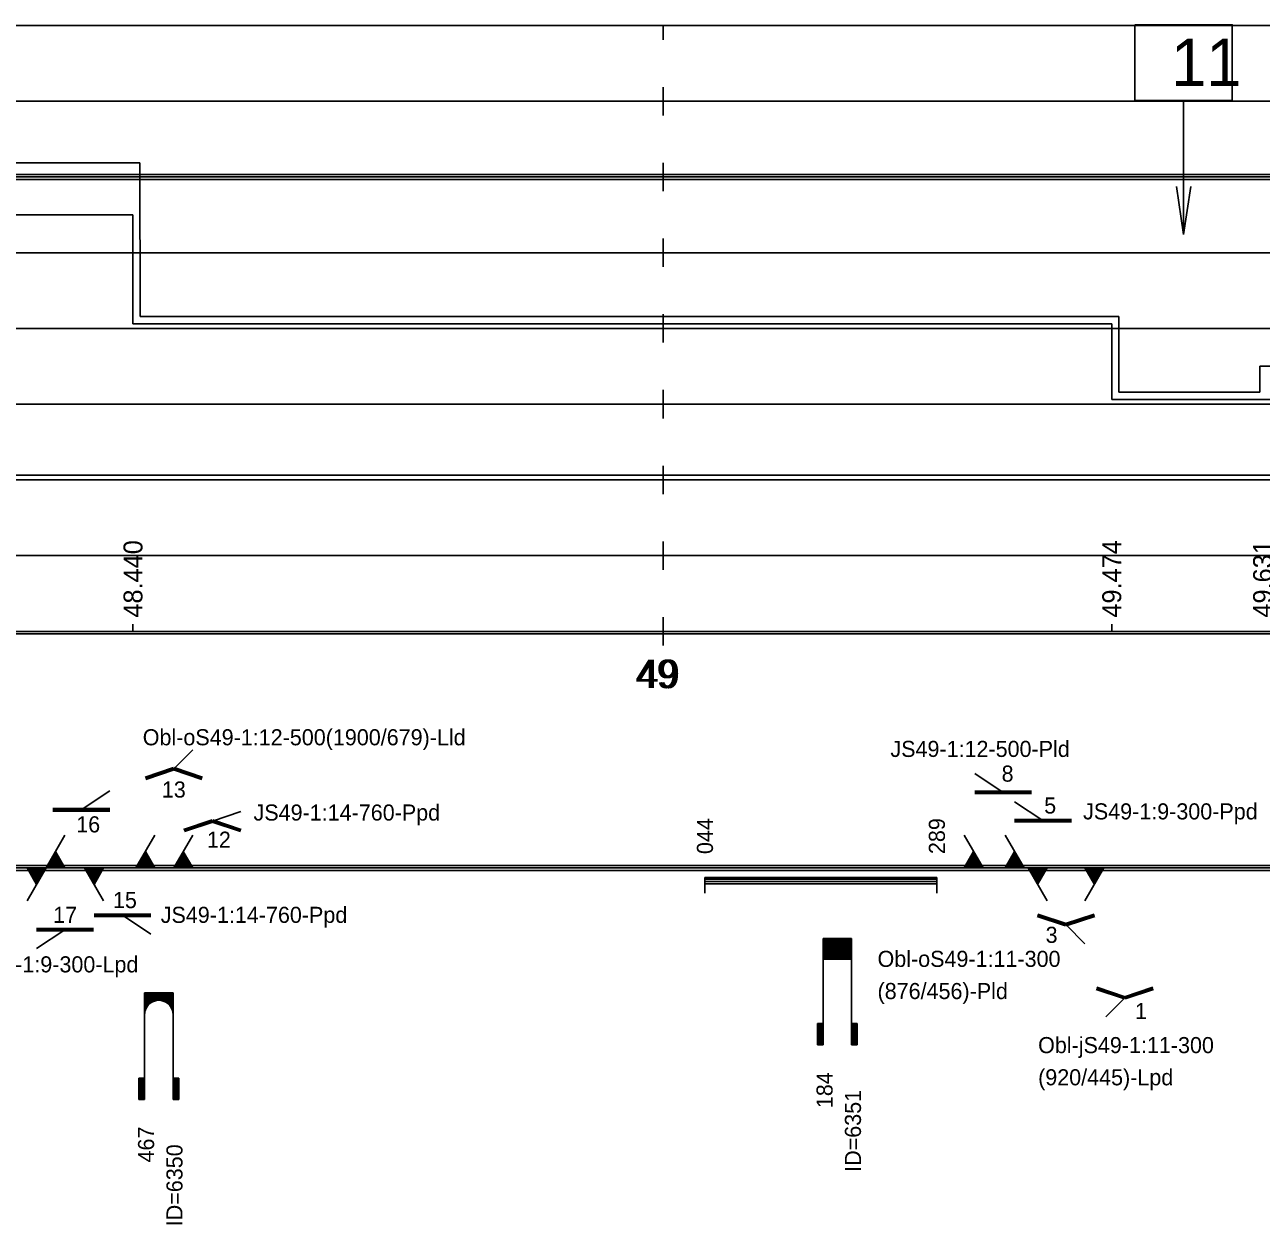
# Model space of a CAD drawing. Extents: x 2 to 10148, y 0 to 380.
# Drawn here: x 5134 to 5264.7, y 87.4 to 214.1 of the extents above; entities that cross this region are included whole.
import ezdxf

# ---------------------------------------------------------------- set-up
doc = ezdxf.new("R2010")
doc.units = 0
for name, color, linetype in [('CARA_S_OBJEKTY', 7, 'Continuous'), ('L_OBJEKTY_TEXT', 7, 'Continuous'), ('L_OBJEKTY_TVAR', 7, 'Continuous'), ('OBJEKTY_TEXT', 7, 'Continuous'), ('OBJEKTY_TVAR', 7, 'Continuous'), ('RYCHL_A', 7, 'Continuous'), ('RYCHL_B', 7, 'Continuous'), ('RYCHL_C', 7, 'Continuous'), ('RYCHL_RASTR', 7, 'Continuous'), ('RYCHL_STAN', 7, 'Continuous'), ('SLOUPEC', 7, 'Continuous'), ('STANIC_ZMEN_V', 7, 'Continuous')]:
    doc.layers.add(name, color=color, linetype=linetype)

msp = doc.modelspace()

# ---------------------------------------------------------------- linework, layer by layer
at = {"layer": 'CARA_S_OBJEKTY'}
for p, q in [((5128.6, 125.25), (5974.91, 125.25)), ((5128.6, 125), (5974.91, 125)), ((5128.6, 124.75), (5974.91, 124.75))]:
    msp.add_line(p, q, dxfattribs=at)
at = {"layer": 'L_OBJEKTY_TVAR'}
for p, q in [((5205.9, 124), (5230.41, 124)), ((5205.9, 122.33), (5205.9, 124)), ((5205.9, 123.83), (5230.41, 123.83)), ((5205.9, 123.58), (5230.41, 123.58)), ((5205.9, 123.33), (5230.41, 123.33)), ((5230.41, 122.33), (5230.41, 124))]:
    msp.add_line(p, q, dxfattribs=at)
at = {"layer": 'OBJEKTY_TVAR'}
for p, q in [((5149.77, 135.48), (5151.77, 137.48)), ((5146.73, 134.6), (5149.73, 135.6)), ((5146.77, 134.48), (5149.77, 135.48)), ((5146.81, 134.36), (5149.81, 135.36)), ((5149.73, 135.36), (5152.73, 134.36)), ((5149.77, 135.48), (5152.77, 134.48)), ((5149.81, 135.6), (5152.81, 134.6)), ((5237.42, 132.99), (5234.42, 134.99)), ((5140, 131.14), (5143, 133.14)), ((5234.42, 133.11), (5240.42, 133.11)), ((5234.42, 132.99), (5240.42, 132.99)), ((5234.42, 132.86), (5240.42, 132.86)), ((5241.62, 130), (5238.62, 132)), ((5137, 131.27), (5143, 131.27)), ((5137, 131.14), (5143, 131.14)), ((5137, 131.02), (5143, 131.02)), ((5153.85, 129.96), (5156.85, 130.96)), ((5150.81, 129.08), (5153.81, 130.08)), ((5150.85, 128.96), (5153.85, 129.96)), ((5150.89, 128.84), (5153.89, 129.84)), ((5153.81, 129.84), (5156.81, 128.84)), ((5153.85, 129.96), (5156.85, 128.96)), ((5153.89, 130.08), (5156.89, 129.08)), ((5238.62, 130.12), (5244.62, 130.12)), ((5238.62, 130), (5244.62, 130)), ((5238.62, 129.88), (5244.62, 129.88)), ((5136.27, 125), (5138.27, 128.46)), ((5145.77, 125), (5147.77, 128.46)), ((5149.77, 125), (5151.77, 128.46)), ((5235.29, 125), (5233.29, 128.46)), ((5239.62, 125), (5237.62, 128.46)), ((5136.92, 125), (5136.59, 125.56)), ((5137.07, 125), (5136.67, 125.69)), ((5137.22, 125), (5136.74, 125.82)), ((5137.37, 125), (5136.82, 125.95)), ((5137.52, 125), (5136.89, 126.08)), ((5137.67, 125), (5136.97, 126.21)), ((5137.82, 125), (5137.04, 126.34)), ((5137.97, 125), (5137.12, 126.47)), ((5138.12, 125), (5137.19, 126.6)), ((5138.27, 125), (5137.27, 126.73)), ((5146.42, 125), (5146.09, 125.56)), ((5146.57, 125), (5146.17, 125.69)), ((5146.72, 125), (5146.24, 125.82)), ((5146.87, 125), (5146.32, 125.95)), ((5147.02, 125), (5146.39, 126.08)), ((5147.17, 125), (5146.47, 126.21)), ((5147.32, 125), (5146.54, 126.34)), ((5147.47, 125), (5146.62, 126.47)), ((5147.62, 125), (5146.69, 126.6)), ((5147.77, 125), (5146.77, 126.73)), ((5150.42, 125), (5150.1, 125.56)), ((5150.57, 125), (5150.17, 125.69)), ((5150.72, 125), (5150.25, 125.82)), ((5150.87, 125), (5150.32, 125.95)), ((5151.02, 125), (5150.4, 126.08)), ((5151.17, 125), (5150.47, 126.21)), ((5151.32, 125), (5150.55, 126.34)), ((5151.47, 125), (5150.62, 126.47)), ((5151.62, 125), (5150.7, 126.6)), ((5151.77, 125), (5150.77, 126.73)), ((5233.29, 125), (5234.29, 126.73)), ((5233.44, 125), (5234.36, 126.6)), ((5233.59, 125), (5234.44, 126.47)), ((5233.74, 125), (5234.51, 126.34)), ((5233.89, 125), (5234.59, 126.21)), ((5234.04, 125), (5234.66, 126.08)), ((5234.19, 125), (5234.74, 125.95)), ((5234.34, 125), (5234.81, 125.82)), ((5234.49, 125), (5234.89, 125.69)), ((5234.64, 125), (5234.96, 125.56)), ((5237.62, 125), (5238.62, 126.73)), ((5237.77, 125), (5238.69, 126.6)), ((5237.92, 125), (5238.77, 126.47)), ((5238.07, 125), (5238.84, 126.34)), ((5238.22, 125), (5238.92, 126.21)), ((5238.37, 125), (5238.99, 126.08)), ((5238.52, 125), (5239.07, 125.95)), ((5238.67, 125), (5239.14, 125.82)), ((5238.82, 125), (5239.22, 125.69)), ((5238.97, 125), (5239.29, 125.56)), ((5134.27, 125), (5135.27, 123.27)), ((5136.27, 125), (5134.27, 121.54)), ((5134.42, 125), (5135.34, 123.4)), ((5134.57, 125), (5135.42, 123.53)), ((5134.72, 125), (5135.49, 123.66)), ((5134.87, 125), (5135.57, 123.79)), ((5135.02, 125), (5135.64, 123.92)), ((5135.17, 125), (5135.72, 124.05)), ((5135.32, 125), (5135.79, 124.18)), ((5135.47, 125), (5135.87, 124.31)), ((5135.62, 125), (5135.94, 124.44)), ((5135.77, 125), (5136.02, 124.57)), ((5135.92, 125), (5136.09, 124.7)), ((5136.07, 125), (5136.17, 124.83)), ((5136.47, 125), (5136.37, 125.17)), ((5136.62, 125), (5136.44, 125.3)), ((5136.77, 125), (5136.52, 125.43)), ((5140.34, 125), (5142.34, 121.54)), ((5140.54, 125), (5140.44, 124.83)), ((5140.69, 125), (5140.51, 124.7)), ((5140.84, 125), (5140.59, 124.57)), ((5140.99, 125), (5140.66, 124.44)), ((5141.14, 125), (5140.74, 124.31)), ((5141.29, 125), (5140.81, 124.18)), ((5141.44, 125), (5140.89, 124.05)), ((5141.59, 125), (5140.96, 123.92)), ((5141.74, 125), (5141.04, 123.79)), ((5141.89, 125), (5141.11, 123.66)), ((5142.04, 125), (5141.19, 123.53)), ((5142.19, 125), (5141.26, 123.4)), ((5142.34, 125), (5141.34, 123.27)), ((5145.97, 125), (5145.87, 125.17)), ((5146.12, 125), (5145.94, 125.3)), ((5146.27, 125), (5146.02, 125.43)), ((5149.97, 125), (5149.87, 125.17)), ((5150.12, 125), (5149.95, 125.3)), ((5150.27, 125), (5150.02, 125.43)), ((5234.79, 125), (5235.04, 125.43)), ((5234.94, 125), (5235.11, 125.3)), ((5235.09, 125), (5235.19, 125.17)), ((5239.12, 125), (5239.37, 125.43)), ((5239.27, 125), (5239.44, 125.3)), ((5239.42, 125), (5239.52, 125.17)), ((5240.06, 125), (5242.06, 121.54)), ((5240.26, 125), (5240.16, 124.83)), ((5240.41, 125), (5240.23, 124.7)), ((5240.56, 125), (5240.31, 124.57)), ((5240.71, 125), (5240.38, 124.44)), ((5240.86, 125), (5240.46, 124.31)), ((5241.01, 125), (5240.53, 124.18)), ((5241.16, 125), (5240.61, 124.05)), ((5241.31, 125), (5240.68, 123.92)), ((5241.46, 125), (5240.76, 123.79)), ((5241.61, 125), (5240.83, 123.66)), ((5241.76, 125), (5240.91, 123.53)), ((5241.91, 125), (5240.98, 123.4)), ((5242.06, 125), (5241.06, 123.27)), ((5246.06, 125), (5247.06, 123.27)), ((5248.06, 125), (5246.06, 121.54)), ((5246.21, 125), (5247.14, 123.4)), ((5246.36, 125), (5247.21, 123.53)), ((5246.51, 125), (5247.29, 123.66)), ((5246.66, 125), (5247.36, 123.79)), ((5246.81, 125), (5247.44, 123.92)), ((5246.96, 125), (5247.51, 124.05)), ((5247.11, 125), (5247.59, 124.18)), ((5247.26, 125), (5247.66, 124.31)), ((5247.41, 125), (5247.74, 124.44)), ((5247.56, 125), (5247.81, 124.57)), ((5247.71, 125), (5247.89, 124.7)), ((5247.86, 125), (5247.96, 124.83)), ((5141.34, 120.12), (5147.34, 120.12)), ((5141.34, 120), (5147.34, 120)), ((5141.34, 119.88), (5147.34, 119.88)), ((5144.34, 120), (5147.34, 118)), ((5241.02, 119.88), (5244.02, 118.88)), ((5241.06, 120), (5244.06, 119)), ((5241.09, 120.12), (5244.09, 119.12)), ((5244.02, 119.12), (5247.02, 120.12)), ((5244.06, 119), (5247.06, 120)), ((5244.06, 119), (5246.06, 117)), ((5244.09, 118.88), (5247.09, 119.88)), ((5135.27, 118.61), (5141.27, 118.61)), ((5135.27, 118.48), (5141.27, 118.48)), ((5138.27, 118.48), (5135.27, 116.48)), ((5135.27, 118.36), (5141.27, 118.36)), ((5218.39, 117.56), (5221.39, 117.56)), ((5218.39, 106.31), (5218.39, 117.56)), ((5218.39, 117.48), (5221.39, 117.48)), ((5218.39, 117.41), (5221.39, 117.41)), ((5218.39, 117.33), (5221.39, 117.33)), ((5218.39, 117.26), (5221.39, 117.26)), ((5218.39, 117.18), (5221.39, 117.18)), ((5218.39, 117.11), (5221.39, 117.11)), ((5218.39, 117.03), (5221.39, 117.03)), ((5218.39, 116.96), (5221.39, 116.96)), ((5218.39, 116.88), (5221.39, 116.88)), ((5218.39, 116.81), (5221.39, 116.81)), ((5218.39, 116.73), (5221.39, 116.73)), ((5218.39, 116.66), (5221.39, 116.66)), ((5218.39, 116.58), (5221.39, 116.58)), ((5218.39, 116.51), (5221.39, 116.51)), ((5218.39, 116.43), (5221.39, 116.43)), ((5218.39, 116.36), (5221.39, 116.36)), ((5221.39, 117.56), (5221.39, 106.31)), ((5218.39, 116.28), (5221.39, 116.28)), ((5218.39, 116.21), (5221.39, 116.21)), ((5218.39, 116.13), (5221.39, 116.13)), ((5218.39, 116.06), (5221.39, 116.06)), ((5218.39, 115.98), (5221.39, 115.98)), ((5218.39, 115.91), (5221.39, 115.91)), ((5218.39, 115.83), (5221.39, 115.83)), ((5218.39, 115.76), (5221.39, 115.76)), ((5218.39, 115.68), (5221.39, 115.68)), ((5218.39, 115.61), (5221.39, 115.61)), ((5218.39, 115.53), (5221.39, 115.53)), ((5218.39, 115.46), (5221.39, 115.46)), ((5218.39, 115.38), (5221.39, 115.38)), ((5247.31, 112.4), (5250.31, 111.4)), ((5250.23, 111.4), (5253.23, 112.4)), ((5146.69, 100.56), (5146.69, 111.81)), ((5149.69, 111.81), (5146.69, 111.81)), ((5146.69, 111.73), (5149.69, 111.73)), ((5146.69, 111.66), (5149.69, 111.66)), ((5146.69, 111.58), (5149.69, 111.58)), ((5146.69, 111.51), (5149.69, 111.51)), ((5146.69, 111.43), (5149.69, 111.43)), ((5146.69, 111.36), (5149.69, 111.36)), ((5146.69, 111.28), (5149.69, 111.28)), ((5146.69, 111.21), (5149.69, 111.21)), ((5146.69, 111.13), (5149.69, 111.13)), ((5149.69, 111.81), (5149.69, 100.56)), ((5247.23, 112.16), (5250.23, 111.16)), ((5247.27, 112.28), (5250.27, 111.28)), ((5250.27, 111.28), (5248.27, 109.28)), ((5250.27, 111.28), (5253.27, 112.28)), ((5250.31, 111.16), (5253.31, 112.16)), ((5146.69, 111.06), (5149.69, 111.06)), ((5146.69, 110.98), (5147.85, 110.98)), ((5146.69, 110.91), (5147.61, 110.91)), ((5146.69, 110.83), (5147.46, 110.83)), ((5146.69, 110.76), (5147.34, 110.76)), ((5146.69, 110.68), (5147.24, 110.68)), ((5146.69, 110.61), (5147.15, 110.61)), ((5146.69, 110.53), (5147.08, 110.53)), ((5146.69, 110.46), (5147.02, 110.46)), ((5146.69, 110.38), (5146.96, 110.38)), ((5146.69, 110.31), (5146.91, 110.31)), ((5146.69, 110.23), (5146.87, 110.23)), ((5146.69, 110.16), (5146.83, 110.16)), ((5146.69, 110.08), (5146.8, 110.08)), ((5146.69, 110.01), (5146.77, 110.01)), ((5146.69, 109.93), (5146.75, 109.93)), ((5146.69, 109.86), (5146.73, 109.86)), ((5146.69, 109.78), (5146.71, 109.78)), ((5146.7, 109.67), (5146.72, 109.84)), ((5146.72, 109.84), (5146.77, 110.02)), ((5146.77, 110.02), (5146.84, 110.17)), ((5146.84, 110.17), (5146.91, 110.31)), ((5146.91, 110.31), (5147.02, 110.46)), ((5147.02, 110.46), (5147.15, 110.61)), ((5147.15, 110.61), (5147.23, 110.68)), ((5147.23, 110.68), (5147.33, 110.75)), ((5147.33, 110.75), (5147.46, 110.83)), ((5147.46, 110.83), (5147.61, 110.91)), ((5147.61, 110.91), (5147.85, 110.98)), ((5147.85, 110.98), (5148.06, 111.02)), ((5148.06, 111.02), (5148.31, 111.02)), ((5148.31, 111.02), (5148.45, 111)), ((5148.45, 111), (5148.53, 110.98)), ((5148.53, 110.98), (5149.69, 110.98)), ((5148.53, 110.98), (5148.77, 110.91)), ((5148.77, 110.91), (5149.69, 110.91)), ((5148.77, 110.91), (5148.92, 110.83)), ((5148.92, 110.83), (5149.69, 110.83)), ((5148.92, 110.83), (5149.04, 110.76)), ((5149.04, 110.76), (5149.69, 110.76)), ((5149.04, 110.76), (5149.14, 110.68)), ((5149.14, 110.68), (5149.69, 110.68)), ((5149.14, 110.68), (5149.23, 110.61)), ((5149.23, 110.61), (5149.69, 110.61)), ((5149.23, 110.61), (5149.3, 110.53)), ((5149.3, 110.53), (5149.69, 110.53)), ((5149.3, 110.53), (5149.36, 110.46)), ((5149.36, 110.46), (5149.68, 110.46)), ((5149.36, 110.46), (5149.42, 110.38)), ((5149.42, 110.38), (5149.69, 110.38)), ((5149.42, 110.38), (5149.51, 110.23)), ((5149.47, 110.31), (5149.69, 110.31)), ((5149.51, 110.23), (5149.69, 110.23)), ((5149.51, 110.23), (5149.58, 110.08)), ((5149.55, 110.16), (5149.69, 110.16)), ((5149.58, 110.08), (5149.69, 110.08)), ((5149.58, 110.08), (5149.63, 109.93)), ((5149.61, 110.01), (5149.69, 110.01)), ((5149.63, 109.93), (5149.69, 109.93)), ((5149.63, 109.93), (5149.67, 109.78)), ((5149.65, 109.86), (5149.69, 109.86)), ((5149.67, 109.78), (5149.69, 109.78)), ((5149.67, 109.78), (5149.69, 109.53)), ((5146.69, 109.71), (5146.7, 109.71)), ((5146.69, 109.53), (5146.7, 109.67)), ((5149.68, 109.71), (5149.69, 109.71)), ((5217.79, 108.56), (5217.79, 106.31)), ((5217.79, 108.56), (5218.39, 108.56)), ((5217.86, 108.56), (5217.86, 106.31)), ((5217.94, 108.56), (5217.94, 106.31)), ((5218.01, 108.56), (5218.01, 106.31)), ((5218.09, 108.56), (5218.09, 106.31)), ((5218.16, 108.56), (5218.16, 106.31)), ((5218.24, 108.56), (5218.24, 106.31)), ((5218.31, 108.56), (5218.31, 106.31)), ((5221.99, 108.56), (5221.39, 108.56)), ((5221.47, 108.56), (5221.47, 106.31)), ((5221.54, 108.56), (5221.54, 106.31)), ((5221.62, 108.56), (5221.62, 106.31)), ((5221.69, 108.56), (5221.69, 106.31)), ((5221.77, 108.56), (5221.77, 106.31)), ((5221.84, 108.56), (5221.84, 106.31)), ((5221.92, 108.56), (5221.92, 106.31)), ((5221.99, 108.56), (5221.99, 106.31)), ((5218.39, 106.31), (5217.79, 106.31)), ((5221.39, 106.31), (5221.99, 106.31)), ((5146.09, 102.81), (5146.69, 102.81)), ((5146.09, 102.81), (5146.09, 100.56)), ((5146.16, 102.81), (5146.16, 100.56)), ((5146.24, 102.81), (5146.24, 100.56)), ((5146.31, 102.81), (5146.31, 100.56)), ((5146.39, 102.81), (5146.39, 100.56)), ((5146.46, 102.81), (5146.46, 100.56)), ((5146.54, 102.81), (5146.54, 100.56)), ((5146.61, 102.81), (5146.61, 100.56)), ((5150.29, 102.81), (5149.69, 102.81)), ((5149.77, 102.81), (5149.77, 100.56)), ((5149.84, 102.81), (5149.84, 100.56)), ((5149.92, 102.81), (5149.92, 100.56)), ((5149.99, 102.81), (5149.99, 100.56)), ((5150.07, 102.81), (5150.07, 100.56)), ((5150.14, 102.81), (5150.14, 100.56)), ((5150.22, 102.81), (5150.22, 100.56)), ((5150.29, 102.81), (5150.29, 100.56)), ((5146.69, 100.56), (5146.09, 100.56)), ((5149.69, 100.56), (5150.29, 100.56))]:
    msp.add_line(p, q, dxfattribs=at)
at = {"layer": 'RYCHL_A'}
msp.add_line((5131.49, 166.5), (5297.49, 166.5), dxfattribs=at)
at = {"layer": 'RYCHL_B'}
for p, q in [((5110.03, 194), (5145.46, 194)), ((5145.46, 194), (5145.46, 182.5)), ((5145.46, 182.5), (5248.89, 182.5)), ((5248.89, 182.5), (5248.89, 174.5)), ((5248.89, 174.5), (5296.74, 174.5))]:
    msp.add_line(p, q, dxfattribs=at)
at = {"layer": 'RYCHL_C'}
for p, q in [((5128.6, 199.5), (5146.17, 199.5)), ((5146.17, 199.5), (5146.21, 183.25)), ((5146.21, 183.25), (5249.64, 183.25)), ((5249.64, 183.25), (5249.64, 175.25)), ((5264.55, 175.25), (5264.55, 178)), ((5264.55, 178), (5295.99, 178)), ((5249.64, 175.25), (5264.55, 175.25))]:
    msp.add_line(p, q, dxfattribs=at)
at = {"layer": 'RYCHL_RASTR'}
for p, q in [((5122.28, 214), (5973.52, 214)), ((5201.49, 212.5), (5201.49, 214)), ((5201.49, 204.5), (5201.49, 207.5)), ((5122.18, 206), (5973.87, 206)), ((5201.49, 196.5), (5201.49, 199.5)), ((5122.4, 198.25), (5973.94, 198.25)), ((5122.4, 198), (5973.94, 198)), ((5122.45, 197.75), (5973.9, 197.75)), ((5201.49, 188.5), (5201.49, 191.5)), ((5122.56, 190), (5974.27, 190)), ((5201.49, 180.5), (5201.49, 183.5)), ((5122.54, 182), (5974.32, 182)), ((5201.49, 172.5), (5201.49, 175.5)), ((5122.71, 174), (5974.23, 174)), ((5201.49, 164.5), (5201.49, 167.5)), ((5122.69, 166), (5974.36, 166)), ((5201.49, 156.5), (5201.49, 159.5)), ((5122.67, 158), (5974.55, 158)), ((5201.49, 148.5), (5201.49, 151.5)), ((5128.6, 150), (5974.91, 150)), ((5128.6, 149.75), (5974.91, 149.75))]:
    msp.add_line(p, q, dxfattribs=at)
at = {"layer": 'SLOUPEC'}
for p, q in [((5256.48, 206.08), (5256.48, 191.93)), ((5256.48, 191.93), (5255.72, 196.98)), ((5256.48, 191.93), (5257.25, 196.98))]:
    msp.add_line(p, q, dxfattribs=at)
msp.add_lwpolyline([(5251.34, 214.08), (5261.63, 214.08), (5261.63, 206.08), (5251.34, 206.08)], close=True, dxfattribs=at)
at = {"layer": 'STANIC_ZMEN_V'}
for p, q in [((5145.46, 150), (5145.46, 150.75)), ((5248.89, 150), (5248.89, 150.75))]:
    msp.add_line(p, q, dxfattribs=at)

# ---------------------------------------------------------------- texts
at = {"layer": 'L_OBJEKTY_TEXT'}
for s, p in [('044', (5206.75, 126.47)), ('289', (5231.26, 126.47))]:
    msp.add_text(s, height=1.7, rotation=90, dxfattribs=at).set_placement(p)
at = {"layer": 'OBJEKTY_TEXT'}
for s, p in [('Obl-oS49-1:12-500(1900/679)-Lld', (5146.49, 137.96)), ('JS49-1:12-500-Pld', (5225.5, 136.73)), ('8', (5237.25, 134.12)), ('13', (5148.51, 132.44)), ('5', (5241.75, 130.75)), ('JS49-1:14-760-Ppd', (5158.2, 130.01)), ('JS49-1:9-300-Ppd', (5245.86, 130.13)), ('16', (5139.46, 128.76)), ('12', (5153.27, 127.14)), ('15', (5143.34, 120.76)), ('17', (5137.02, 119.2)), ('JS49-1:14-760-Ppd', (5148.39, 119.2)), ('3', (5241.9, 117.09)), ('Obl-oS49-1:11-300', (5224.14, 114.55)), ('JS49-1:9-300-Lpd', (5127.83, 113.97)), ('(876/456)-Pld', (5224.14, 111.15)), ('1', (5251.35, 109.04)), ('Obl-jS49-1:11-300', (5241.11, 105.44)), ('(920/445)-Lpd', (5241.11, 102.04))]:
    msp.add_text(s, height=1.7, dxfattribs=at).set_placement(p)
for s, p in [('184', (5219.39, 99.63)), ('ID=6351', (5222.39, 92.9)), ('467', (5147.69, 93.89)), ('ID=6350', (5150.69, 87.15))]:
    msp.add_text(s, height=1.7, rotation=90, dxfattribs=at).set_placement(p)
at = {"layer": 'RYCHL_STAN'}
for p in [(5198.55, 144), (5198.8, 144)]:
    msp.add_text('49', height=3, dxfattribs=at).set_placement(p)
at = {"layer": 'SLOUPEC'}
msp.add_text('11', height=5, dxfattribs=at).set_placement((5255.16, 207.61))
at = {"layer": 'STANIC_ZMEN_V'}
for s, p in [('48.440', (5146.46, 151.45)), ('49.474', (5249.89, 151.45)), ('49.631', (5265.83, 151.45))]:
    msp.add_text(s, height=2, rotation=90, dxfattribs=at).set_placement(p)

doc.saveas('drawing.dxf')
